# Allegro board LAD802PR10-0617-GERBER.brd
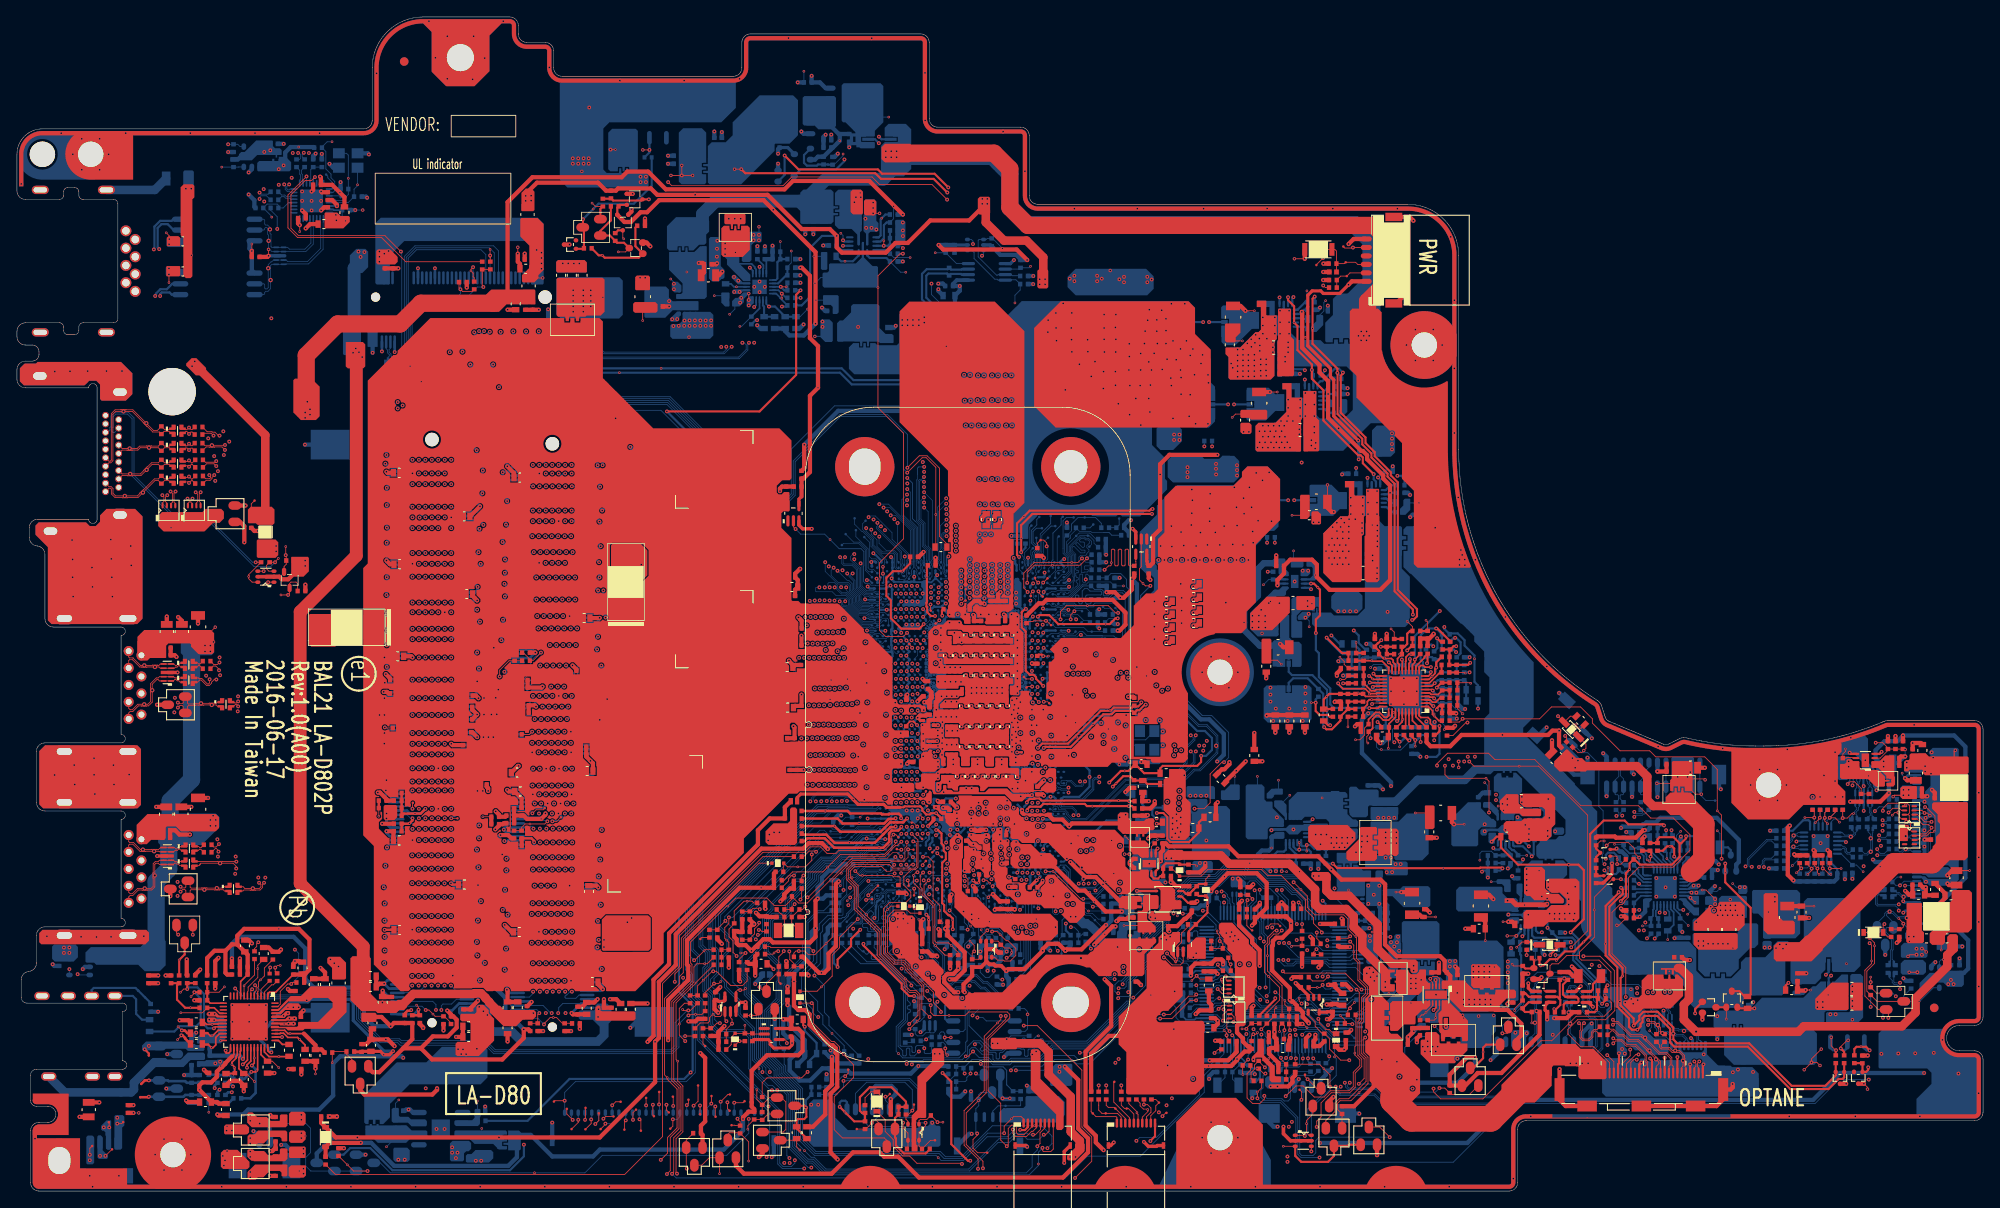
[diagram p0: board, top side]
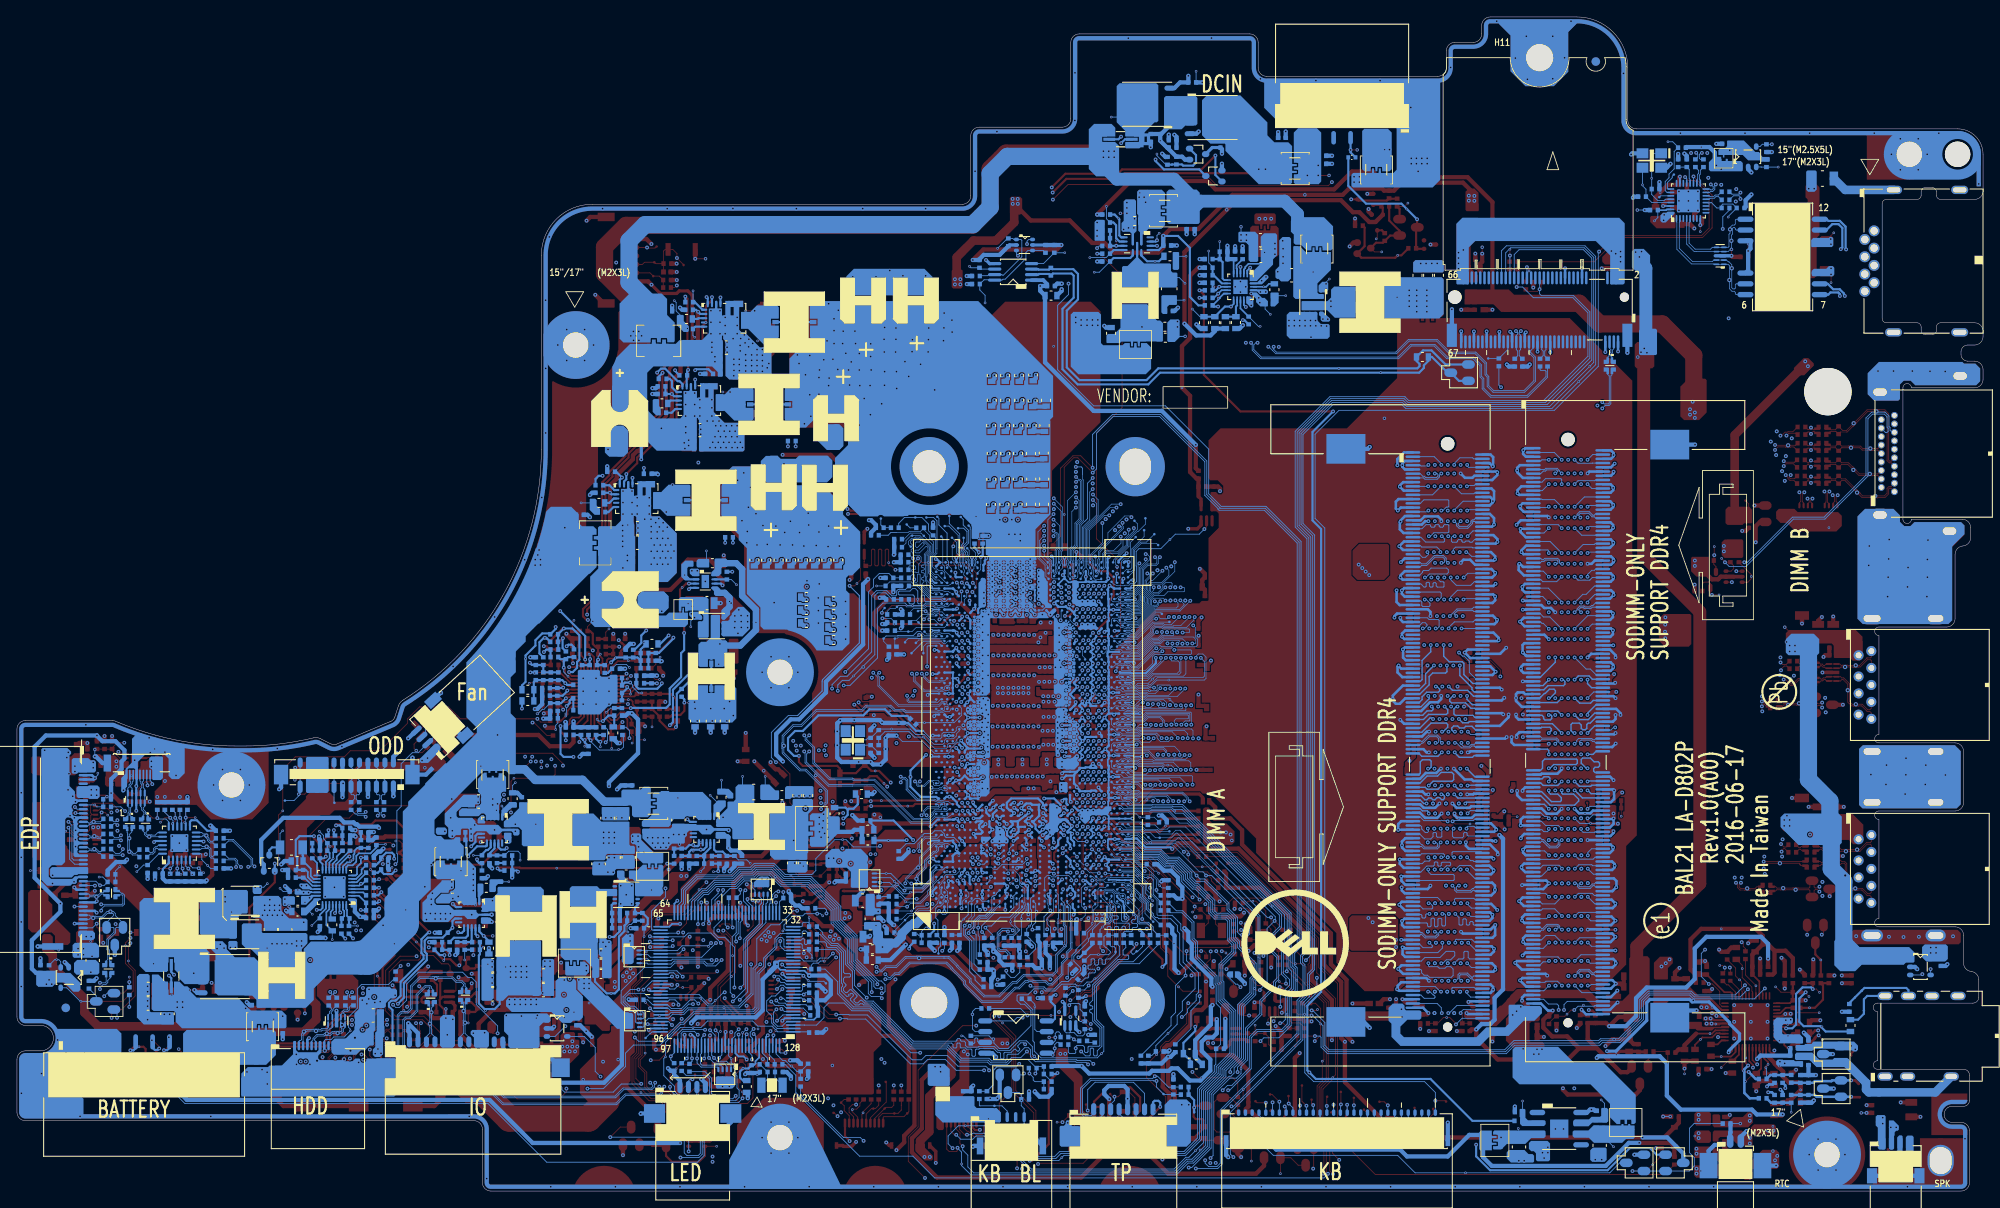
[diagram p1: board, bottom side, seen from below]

Outline 231.9 x 138.5 mm; copper layers: TOP, VCC, IN1, IN2, GND, BOTTOM. Coordinates in mm from the lower left corner of the outline.
Outline path: 0,122.3 0,117.98 arc(0.29,117.27) 1,116.98 5,116.98 arc(5.35,117.12) 5.5,117.48 5.5,117.88 arc(5.65,118.23) 6,118.38 6.8,118.38 arc(7.15,118.23) 7.3,117.88 7.3,117.48 arc(7.45,117.12) 7.8,116.98 11.4,116.98 arc(11.75,116.83) 11.9,116.48 11.9,102.92 arc(11.75,102.57) 11.4,102.42 7.8,102.42 arc(7.45,102.28) 7.3,101.92 7.3,101.52 arc(7.15,101.17) 6.8,101.02 6,101.02 arc(5.65,101.17) 5.5,101.52 5.5,101.92 arc(5.35,102.28) 5,102.42 1,102.42 arc(0.29,102.13) 0,101.42 0,100.8 arc(0.29,100.09) 1,99.8 1.8,99.8 arc(2.37,99.57) 2.6,99 2.6,98.7 arc(2.37,98.13) 1.8,97.9 1,97.9 arc(0.29,97.61) 0,96.9 0,95.75 arc(0.29,95.04) 1,94.75 8.45,94.75 arc(8.95,95.25) 9.45,94.75 9.45,79.25 arc(8.95,78.75) 8.45,79.25 2.46,79.25 arc(1.75,78.96) 1.46,78.25 1.46,77.09 arc(1.73,76.42) 2.38,76.1 arc(3.03,75.78) 3.3,75.1 3.3,67.53 arc(3.59,66.83) 4.3,66.53 12.28,66.53 arc(12.78,66.03) 12.28,65.53 12.28,53.87 arc(12.78,53.37) 12.28,52.87 3.3,52.87 arc(2.59,52.57) 2.3,51.87 2.3,45.83 arc(2.59,45.13) 3.3,44.83 12.28,44.83 arc(12.78,44.33) 12.28,43.83 12.28,32.17 arc(12.78,31.67) 12.28,31.17 3.3,31.17 arc(2.59,30.87) 2.3,30.17 2.3,26.9 arc(2.04,26.23) 1.4,25.9 arc(0.76,25.58) 0.5,24.91 0.5,22.87 arc(0.71,22.37) 1.2,22.17 12.45,22.17 arc(12.95,21.67) 12.45,21.17 12.45,15.37 arc(12.95,14.87) 12.45,14.37 2.3,14.37 arc(1.8,14.16) 1.6,13.67 1.6,10.7 arc(1.8,10.21) 2.3,10 3.65,10 arc(4.6,9.05) 3.65,8.1 2.6,8.1 arc(1.89,7.81) 1.6,7.1 1.6,1 arc(1.89,0.29) 2.6,0 176,0 arc(176.71,0.29) 177,1 177,7.3 arc(177.29,8.01) 178,8.3 230.9,8.3 arc(231.61,8.59) 231.9,9.3 231.9,15.54 arc(231.61,16.25) 230.9,16.54 229.1,16.54 arc(227.6,18.04) 229.1,19.54 230.9,19.54 arc(231.61,19.83) 231.9,20.54 231.9,54.5 arc(231.61,55.21) 230.9,55.5 220.64,55.5 arc(220.44,55.48) 220.25,55.42 arc(213.3,53.24) 206.05,52.5 205.05,52.5 arc(200.96,52.74) 196.92,53.46 arc(196.5,53.48) 196.1,53.36 194.85,52.74 arc(194.52,52.66) 194.19,52.72 187.79,55.41 arc(187.51,55.61) 187.34,55.9 186.91,57.23 arc(186.71,57.6) 186.41,57.88 arc(174.41,70.58) 170.05,87.5 170.05,110.4 arc(168.29,114.64) 164.05,116.4 120.4,116.4 arc(119.69,116.69) 119.4,117.4 119.4,124.5 arc(119.11,125.21) 118.4,125.5 108.6,125.5 arc(107.89,125.79) 107.6,126.5 107.6,135.5 arc(107.31,136.21) 106.6,136.5 86.5,136.5 arc(85.79,136.21) 85.5,135.5 85.5,132.5 arc(85.21,131.79) 84.5,131.5 64.3,131.5 arc(63.59,131.79) 63.3,132.5 63.3,134.5 arc(63.01,135.21) 62.3,135.5 60.13,135.5 arc(59.43,135.79) 59.13,136.5 59.13,137.5 arc(58.84,138.21) 58.13,138.5 47.9,138.5 arc(43.66,136.74) 41.9,132.5 41.9,126.3 arc(41.61,125.59) 40.9,125.3 3,125.3 arc(0.88,124.42) 0,122.3

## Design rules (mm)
net group 10: nets NCT7718_DXN NCT7718_DXP
net group AS-PECI: nets PECI_EC PECI_MEC1404
net group AS-PROCHOT#: nets H_PROCHOT# H_PROCHOT#_R
net group AS-VCCST_PWRGOOD: nets H_VCCST_PWRGD VCCST_PWRGD
net group CLK_PCIE_LAN_N2: nets CLK_PCIE_LAN_N2 CLK_PCIE_LAN_P2
net group CLK_PCIE_SSD_P3: nets CLK_PCIE_SSD_N3 CLK_PCIE_SSD_P3
net group CLK_PCIE_WLAN_N1: nets CLK_PCIE_WLAN_N1 CLK_PCIE_WLAN_P1
net group DDR_A_CLK0: nets DDR_A_CLK0 DDR_A_CLK#0
net group DDR_A_CLK1: nets DDR_A_CLK1 DDR_A_CLK#1
net group DDR_A_DQS0: nets DDR_A_DQS0 DDR_A_DQS#0
net group DDR_A_DQS1: nets DDR_A_DQS1 DDR_A_DQS#1
net group DDR_A_DQS2: nets DDR_A_DQS2 DDR_A_DQS#2
net group DDR_A_DQS3: nets DDR_A_DQS3 DDR_A_DQS#3
net group DDR_A_DQS4: nets DDR_A_DQS4 DDR_A_DQS#4
net group DDR_A_DQS5: nets DDR_A_DQS5 DDR_A_DQS#5
net group DDR_A_DQS6: nets DDR_A_DQS6 DDR_A_DQS#6
net group DDR_A_DQS7: nets DDR_A_DQS7 DDR_A_DQS#7
net group DDR_B_CLK0: nets DDR_B_CLK0 DDR_B_CLK#0
net group DDR_B_CLK1: nets DDR_B_CLK1 DDR_B_CLK#1
net group DDR_B_DQS0: nets DDR_B_DQS0 DDR_B_DQS#0
net group DDR_B_DQS1: nets DDR_B_DQS1 DDR_B_DQS#1
net group DDR_B_DQS2: nets DDR_B_DQS2 DDR_B_DQS#2
net group DDR_B_DQS3: nets DDR_B_DQS3 DDR_B_DQS#3
net group DDR_B_DQS4: nets DDR_B_DQS4 DDR_B_DQS#4
net group DDR_B_DQS5: nets DDR_B_DQS5 DDR_B_DQS#5
net group DDR_B_DQS6: nets DDR_B_DQS6 DDR_B_DQS#6
net group DDR_B_DQS7: nets DDR_B_DQS7 DDR_B_DQS#7
net group DIFFPAIR0: nets DMIC_CLK_EDP DMIC_DATA_EDP
net group EDP_AUX: nets EDP_AUX EDP_AUX#
net group EDP_AUX_D: nets EDP_AUX_DN EDP_AUX_DP
net group EDP_TX0: nets EDP_TX0 EDP_TX0#
net group EDP_TX0_D: nets EDP_TX0_DN EDP_TX0_DP
net group EDP_TX1: nets EDP_TX1 EDP_TX1#
net group EDP_TX1_D: nets EDP_TX1_DN EDP_TX1_DP
net group HDA_CBN/CBP/CPVEE: nets CBP CPVEE
net group HDMI_CLK: nets HDMI_CLK HDMI_CLK#
net group HDMI_CLK_R: nets HDMI_CLK#_R HDMI_CLK_R
net group HDMI_CLK_R_C: nets HDMI_CLK#_R_C HDMI_CLK_R_C
net group HDMI_DATA0: nets HDMI_DATA0 HDMI_DATA0#
net group HDMI_DATA0_R: nets HDMI_DATA0#_R HDMI_DATA0_R
net group HDMI_DATA0_R_C: nets HDMI_DATA0#_R_C HDMI_DATA0_R_C
net group HDMI_DATA1: nets HDMI_DATA1 HDMI_DATA1#
net group HDMI_DATA1_R: nets HDMI_DATA1#_R HDMI_DATA1_R
net group HDMI_DATA1_R_C: nets HDMI_DATA1#_R_C HDMI_DATA1_R_C
net group HDMI_DATA2: nets HDMI_DATA2 HDMI_DATA2#
net group HDMI_DATA2_R: nets HDMI_DATA2#_R HDMI_DATA2_R
net group HDMI_DATA2_R_C: nets HDMI_DATA2#_R_C HDMI_DATA2_R_C
net group LAN_MDI0: nets LAN_MDI0N LAN_MDI0P
net group LAN_MDI1: nets LAN_MDI1N LAN_MDI1P
net group LAN_TXN_C_PCH_RXN6: nets LAN_TXN_C_PCH_RXN6 LAN_TXP_C_PCH_RXP6
net group MDO0: nets MDO0+ MDO0-
net group MDO1: nets MDO1+ MDO1-
net group PCH_SMBCLK: nets PCH_SMBCLK PCH_SMBDATA
net group PCIE RCOMP / IREF: nets PCIE_RCOMPN PCIE_RCOMPP
net group PCIE_CRX_LANTX_6: nets PCIE_CRX_LANTX_N6 PCIE_CRX_LANTX_P6
net group PCIE_CRX_SSDTX_N12: nets PCIE_CRX_SSDTX_N12 PCIE_CRX_SSDTX_P12
net group PCIE_CRX_SSDTX_P11: nets PCIE_CRX_SSDTX_N11 PCIE_CRX_SSDTX_P11
net group PCIE_CTX_C_SSDRX_N11: nets PCIE_CTX_C_SSDRX_N11 PCIE_CTX_C_SSDRX_P11
net group PCIE_CTX_C_SSDRX_N12: nets PCIE_CTX_C_SSDRX_N12 PCIE_CTX_C_SSDRX_P12
net group PCIE_CTX_LANRX_6: nets PCIE_CTX_LANRX_N6 PCIE_CTX_LANRX_P6
net group PCIE_CTX_SSDRX_P12: nets PCIE_CTX_SSDRX_N12 PCIE_CTX_SSDRX_P12
net group PLATFORM CLOCK-DIFF: nets CLK_ITPXDP_N CLK_ITPXDP_P
net group SATA3_CRX_HDDTX_0: nets SATA3_CRX_HDDTX_N0 SATA3_CRX_HDDTX_P0
net group SATA3_CTX_HDDRX_0: nets SATA3_CTX_HDDRX_N0 SATA3_CTX_HDDRX_P0
net group SATA_CRX_ODDTX_1: nets SATA_CRX_ODDTX_N1 SATA_CRX_ODDTX_P1
net group SATA_CTX_ODDRX_1: nets SATA_CTX_ODDRX_N1 SATA_CTX_ODDRX_P1
net group SATA_RX0_R: nets SATA_RXN0_R SATA_RXP0_R
net group SATA_RX2_R: nets SATA_RXN2_R SATA_RXP2_R
net group SATA_TX0_R: nets SATA_TXN0_R SATA_TXP0_R
net group SATA_TX2_R: nets SATA_TXN2_R SATA_TXP2_R
net group SMBCLK: nets SMBCLK SMBDATA
net group SML1CLK: nets SML1CLK SML1DATA
net group THM_SML1_CLK: nets THM_SML1_CLK THM_SML1_DATA
net group USB3_CRX_C_RD_DTX_3: nets USB3_CRX_C_RD_DTX_N3 USB3_CRX_C_RD_DTX_P3
net group USB3_CRX_DTX_1: nets USB3_CRX_DTX_N1 USB3_CRX_DTX_P1
net group USB3_CRX_DTX_1_C: nets USB3_CRX_DTX_N1_C USB3_CRX_DTX_P1_C
net group USB3_CRX_DTX_2: nets USB3_CRX_DTX_N2 USB3_CRX_DTX_P2
net group USB3_CRX_DTX_2_C: nets USB3_CRX_DTX_N2_C USB3_CRX_DTX_P2_C
net group USB3_CRX_DTX_3: nets USB3_CRX_DTX_N3 USB3_CRX_DTX_P3
net group USB3_CRX_L_DTX_3: nets USB3_CRX_L_DTX_N3 USB3_CRX_L_DTX_P3
net group USB3_CRX_RD_DTX_3: nets USB3_CRX_RD_DTX_N3 USB3_CRX_RD_DTX_P3
net group USB3_CTX_C_DRX_3: nets USB3_CTX_C_DRX_N3 USB3_CTX_C_DRX_P3
net group USB3_CTX_C_RD_DRX_3: nets USB3_CTX_C_RD_DRX_N3 USB3_CTX_C_RD_DRX_P3
net group USB3_CTX_DRX_1: nets USB3_CTX_DRX_N1 USB3_CTX_DRX_P1
net group USB3_CTX_DRX_1_C: nets USB3_CTX_DRX_N1_C USB3_CTX_DRX_P1_C
net group USB3_CTX_DRX_1_R: nets USB3_CTX_DRX_N1_R USB3_CTX_DRX_P1_R
net group USB3_CTX_DRX_2: nets USB3_CTX_DRX_N2 USB3_CTX_DRX_P2
net group USB3_CTX_DRX_2_C: nets USB3_CTX_DRX_N2_C USB3_CTX_DRX_P2_C
net group USB3_CTX_DRX_2_R: nets USB3_CTX_DRX_N2_R USB3_CTX_DRX_P2_R
net group USB3_CTX_DRX_3: nets USB3_CTX_DRX_N3 USB3_CTX_DRX_P3
net group USB3_CTX_L_DRX_3: nets USB3_CTX_L_DRX_N3 USB3_CTX_L_DRX_P3
net group USB3_CTX_RD_DRX_3: nets USB3_CTX_RD_DRX_N3 USB3_CTX_RD_DRX_P3
net group USB_CAMERA_EDP: nets USB_CAMERA_EDP USB_CAMERA_EDP#
net group USB_P1: nets USB_PN1 USB_PP1
net group USB_P1_C: nets USB_PN1_C USB_PP1_C
net group USB_P2: nets USB_PN2 USB_PP2
net group USB_P2_C: nets USB_PN2_C USB_PP2_C
net group USB_P3: nets USB_PN3 USB_PP3
net group USB_P3_C: nets USB_PN3_C USB_PP3_C
net group USB_P5: nets USB_PN5 USB_PP5
net group USB_P7: nets USB_PN7 USB_PP7
net group USB_P8: nets USB_PN8 USB_PP8
net group USB_P8_R: nets USB_PN8_R USB_PP8_R
net group USB_PN7_TPNL: nets USB_PN7_TPNL USB_PP7_TPNL
net group AS-BPM#[3:0]: nets XDP_OBS0_R XDP_OBS1_R XDP_OBS2_R XDP_OBS3_R
net group AS-CATERR#: nets H_CATERR#
net group AS-SVID: nets H_CPU_SVIDALRT# VIDALERT_N VIDSCLK VIDSOUT
net group AS-THERMTRIP#: nets H_THERMTRIP#
net group DDR_COMP_20_25: nets SM_RCOMP0 SM_RCOMP1 SM_RCOMP2
net group DDR_RESET: nets DDR4_DRAMRST#
net group DDRADD_10(11)_20: nets DDR_A_ACT# DDR_A_ALERT# DDR_A_BG0 DDR_A_BG1 DDR_A_BS0 DDR_A_BS1 DDR_A_CAS# DDR_A_MA0 DDR_A_MA1 DDR_A_MA2 DDR_A_MA3 DDR_A_MA4 DDR_A_MA5 DDR_A_MA6 DDR_A_MA7 DDR_A_MA8 DDR_A_MA9 DDR_A_MA10 DDR_A_MA11 DDR_A_MA12 DDR_A_MA13 DDR_A_PAR DDR_A_RAS# DDR_A_WE# DDR_B_ACT# DDR_B_ALERT# DDR_B_BG0 DDR_B_BG1 DDR_B_BS0 DDR_B_BS1 DDR_B_CAS# DDR_B_MA0 DDR_B_MA1 DDR_B_MA2 DDR_B_MA3 DDR_B_MA4 DDR_B_MA5 DDR_B_MA6 DDR_B_MA7 DDR_B_MA8 DDR_B_MA9 DDR_B_MA10 DDR_B_MA11 DDR_B_MA12 DDR_B_MA13 DDR_B_PAR DDR_B_RAS# DDR_B_WE#
net group DDRB_D3: nets DDR_B_D24 DDR_B_D25 DDR_B_D26 DDR_B_D27 DDR_B_D28 DDR_B_D29 DDR_B_D30 DDR_B_D31
net group DDRCTL_10(11)_20: nets DDR_A_CKE0 DDR_A_CKE1 DDR_A_CKE2 DDR_A_CKE3 DDR_A_CS#0 DDR_A_CS#1 DDR_A_ODT0 DDR_A_ODT1 DDR_B_CKE0 DDR_B_CKE1 DDR_B_CKE2 DDR_B_CKE3 DDR_B_CS#0 DDR_B_CS#1 DDR_B_ODT0 DDR_B_ODT1
net group DDRD0_19(8.5)_20: nets DDR_A_D0 DDR_A_D1 DDR_A_D2 DDR_A_D3 DDR_A_D4 DDR_A_D5 DDR_A_D6 DDR_A_D7 DDR_A_D16 DDR_A_D17 DDR_A_D18 DDR_A_D19 DDR_A_D20 DDR_A_D21 DDR_A_D22 DDR_A_D23 DDR_A_D32 DDR_A_D33 DDR_A_D34 DDR_A_D35 DDR_A_D36 DDR_A_D37 DDR_A_D38 DDR_A_D39 DDR_A_D48 DDR_A_D49 DDR_A_D50 DDR_A_D51 DDR_A_D52 DDR_A_D53 DDR_A_D54 DDR_A_D55 DDR_B_D0 DDR_B_D1 DDR_B_D2 DDR_B_D3 DDR_B_D4 DDR_B_D5 DDR_B_D6 DDR_B_D7 DDR_B_D16 DDR_B_D17 DDR_B_D18 DDR_B_D19 DDR_B_D20 DDR_B_D21 DDR_B_D22 DDR_B_D23 DDR_B_D32 DDR_B_D33 DDR_B_D34 DDR_B_D35 DDR_B_D36 DDR_B_D37 DDR_B_D38 DDR_B_D39 DDR_B_D48 DDR_B_D49 DDR_B_D50 DDR_B_D51 DDR_B_D52 DDR_B_D53 DDR_B_D54 DDR_B_D55
net group DDRD1_19(8.5)_20: nets DDR_A_D8 DDR_A_D9 DDR_A_D10 DDR_A_D11 DDR_A_D12 DDR_A_D13 DDR_A_D14 DDR_A_D15 DDR_A_D24 DDR_A_D25 DDR_A_D26 DDR_A_D27 DDR_A_D28 DDR_A_D29 DDR_A_D30 DDR_A_D31 DDR_A_D40 DDR_A_D41 DDR_A_D42 DDR_A_D43 DDR_A_D44 DDR_A_D45 DDR_A_D46 DDR_A_D47 DDR_A_D56 DDR_A_D57 DDR_A_D58 DDR_A_D59 DDR_A_D60 DDR_A_D61 DDR_A_D62 DDR_A_D63 DDR_B_D8 DDR_B_D9 DDR_B_D10 DDR_B_D11 DDR_B_D12 DDR_B_D13 DDR_B_D14 DDR_B_D15 DDR_B_D40 DDR_B_D41 DDR_B_D42 DDR_B_D43 DDR_B_D44 DDR_B_D45 DDR_B_D46 DDR_B_D47 DDR_B_D56 DDR_B_D57 DDR_B_D58 DDR_B_D59 DDR_B_D60 DDR_B_D61 DDR_B_D62 DDR_B_D63
net group EDP_COMP: nets EDP_COMP
net group HDA HEADPHONE JACK: nets RING2 RING2_R SLEEVE_R
net group HDA SPEAKER: nets AUD_SPK_L+ AUD_SPK_L+_C AUD_SPK_L- AUD_SPK_L-_C AUD_SPK_R+ AUD_SPK_R+_C AUD_SPK_R- AUD_SPK_R-_C
net group HDA_ANALOG IO: nets AUD_HP1_JACK_L AUD_HP1_JACK_L1 AUD_HP1_JACK_R AUD_HP1_JACK_R1 CBN HPOUT_L HPOUT_R LINE1-L_C LINE1-L_R LINE1_L LINE1_R
net group HDMI_DDC: nets DDC_CLK_HDMI DDC_DATA_HDMI PCH_HDMI_CLK PCH_HDMI_DATA
net group HIGH DEFINITION AUDIO: nets DMIC_CLK HDA_BIT_CLK HDA_CODEC_BITCLK HDA_CODEC_RST# HDA_CODEC_SDOUT HDA_CODEC_SYNC HDA_RST# HDA_SDIN0 HDA_SDOUT HDA_SYNC
net group I2C: nets I2C_SCL_TP I2C_SCL_TP_Q I2C_SDA_TP I2C_SDA_TP_Q
net group KB: nets KSI0 KSI1 KSI2 KSI3 KSI4 KSI5 KSI6 KSI7 KSO0 KSO1 KSO2 KSO3 KSO4 KSO5 KSO6 KSO7 KSO8 KSO9 KSO10 KSO11 KSO12 KSO13 KSO14 KSO15 KSO16
net group LPC: nets CLK_PCI_LPC_MEC LPC_LAD0 LPC_LAD1 LPC_LAD2 LPC_LAD3 LPC_LFRAME#
net group PCIE: nets PCIE_CRX_WLANTX_N5 PCIE_CRX_WLANTX_P5 PCIE_CTX_SSDRX_N11 PCIE_CTX_WLANRX_N5 PCIE_CTX_WLANRX_N5_C PCIE_CTX_WLANRX_P5 PCIE_CTX_WLANRX_P5_C PCIE_PTX_LANRX_P6_C
net group PCIE_CTX_SSDRX_N11: nets PCIE_CTX_SSDRX_P11
net group PCIE_PTX_LANRX_6_C: nets PCIE_PTX_LANRX_N6_C
net group RTC: nets PCH_RTCRST# PCH_RTCX1 PCH_RTCX2 PCH_RTCX2_R SRTCRST# SUSCLK
net group SMBUS: nets PCH_SMB_ALERT# SML0_SMBCLK SML0_SMBDATA
net group SPI: nets EC_SPI_CLK EC_SPI_CS0# EC_SPI_MISO EC_SPI_MOSI PCH_SPI_CLK_0_R PCH_SPI_CLK_R PCH_SPI_CLK_R1 PCH_SPI_CS#0_R1 PCH_SPI_D0_0_R PCH_SPI_D0_R PCH_SPI_D0_R1 PCH_SPI_D1_0_R PCH_SPI_D1_R PCH_SPI_D1_R1 PCH_SPI_D2_0_R PCH_SPI_D2_R PCH_SPI_D2_R1 PCH_SPI_D3_0_R PCH_SPI_D3_R PCH_SPI_D3_R1
net group SRCCLKREQ/ CLKOUT_LPC: nets CLK_PCIE_LAN_REQ# CLK_PCIE_LAN_REQ#_R CLK_PCIE_WLAN_REQ# CLK_PCIE_WLAN_REQ#_R PCI_CLK_LPC1
net group USB20: nets USB_PN6 USB_PN6_C USB_PP6 USB_PP6_C
net group XCLK_BIASREF: nets XCLK_BIASREF
net group XDP: nets CPU_XDP_TCK0 PCH_JTAG_TCK1 PCH_RSMRST#_Q SOC_XDP_TDI SOC_XDP_TDO SOC_XDP_TMS SOC_XDP_TRST# XDP_HOOK0 XDP_ITP_PMODE XDP_PRDY# XDP_PREQ# XDP_PRSENT_CPU XDP_SPI_IO2 XDP_SPI_SI
net group XDP_OBS_CLK_1P: nets CFG16 CFG17 CFG18 CFG19
net group XDP_OBSDATA: nets CFG0 CFG1 CFG2 CFG3 CFG4 CFG5 CFG6 CFG7 CFG8 CFG9 CFG10 CFG11 CFG12 CFG13 CFG14 CFG15 CFG_RCOMP
net group XTAL24_IN/OUT: nets XTAL24_IN XTAL24_OUT XTAL24_OUT_R
nets with their own width: min track width 0.254; nets +1.0V_APLL +1.0V_VCCST +1.0V_VCCST_C +1.0V_VCCSTG +1.0V_VCCSTG_C +1.8V_PRIM +3.3V_ALW_DSW +3.3V_SPI +3VLP +TP_VDD
nets with their own width: min track width 0.381; nets +1.8V_AVDD +1.8V_CPVDD
nets with their own width: min track width 0.508; nets +1.0V_AMPHYPLL +1.0V_APLLEBB +1.0V_MPHYGT +1.0V_PRIM +1.0V_SRAM +1.0VS_VCCIO +1.0VS_VCCOPC +1.2VP +2.5VP +3V_DVDD +3VALW +3VALW_PCH +3VALWP +3VS +3VS_CAM +5V_CAM +5V_KB_BL +5VALW +5VALWP +5VS +19VB +DCBAT_LCD +LAN_VDD10 +LAN_VDDREG +RTC_CELL +V_DDR_REFA +V_DDR_REFA_R +VCC_CORE +VCC_GT +VCC_SA AUD_AGND GND IR_GND
nets with their own width: min track width 1.016; nets +TPAN_VDD +TPAN_VDD_F
nets with their own width: min track width 1.524; nets +0.6VSP +5V_AVDD
nets with their own width: min track width 2.032; nets +3.3V_WLAN USB20_VCCA USB30_VCCA
nets with their own width: min track width 2.413; nets +LCDVDD_LCD
nets with their own width: min track width 2.54; nets +5V_PVDD

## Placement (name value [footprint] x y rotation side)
C1  0.47U_0402_6.3V6K  [C_0402]  35.88 8.79 0 top
C2  0.1U_0402_16V7K  [C_0402]  223.78 47.46 0 top
C3  1U_0402_10V6K  [C_0402]  223.78 46.57 0 top
C4  0.1U_0603_50V7K  [C_0603]  224.75 51.27 90 top
C5  1000P_0402_50V7K  [C_0402]  223.6 51.19 90 top
C6  0.1U_0402_16V7K  [C_0402]  220.8 42.12 0 bottom
C7  0.1U_0402_16V7K  [C_0402]  220.8 41.24 0 bottom
C8  0.1U_0402_16V7K  [C_0402]  220.8 40.35 0 bottom
C9  0.1U_0402_16V7K  [C_0402]  220.8 39.46 0 bottom
C10  0.1U_0402_16V7K  [C_0402]  220.8 43.01 0 bottom
C11  0.1U_0402_16V7K  [C_0402]  220.8 43.9 0 bottom
C13  10P_0402_50V8J  [C_0402]  220.29 37.36 0 bottom
C14  33P_0402_50V8J  [C_0402]  224.49 36.14 180 top
C15  4.7U_0603_6.3V6K  [C_0603]  225 34.94 180 top
C16  10P_0402_50V8J  [C_0402]  222.01 30.9 270 top
C17  1U_0402_6.3V6K  [C_0402]  229.13 25.72 90 bottom
C18  .1U_0402_16V7K  [C_0402]  87.9 8.39 90 top
C19  0.1U_0402_16V7K  [C_0402]  103.98 9.93 180 top
C20  10U_0603_6.3V6M  [C_0603]  110.64 105.63 180 bottom
C21  0.1U_0402_16V7K  [C_0402]  110.4 106.76 180 bottom
C22  470P_0603_50V8J  [C_0603]  65.43 98.39 0 bottom
C23  2200P_0402_50V7K  [C_0402]  109.95 107.99 90 bottom
C24  0.1U_0402_16V7K  [C_0402]  118.33 106.99 0 bottom
C25  0.1U_0402_16V7K  [C_0402]  118.33 107.94 0 bottom
C26  10P_0402_50V8J  [C_0402]  95.5 12.25 90 bottom
C27  10P_0402_50V8J  [C_0402]  95.5 11.39 270 bottom
C30  22U_0805_10V6M  [C_0805]  182.17 50.47 135 top
C32  0.1U_0402_16V7K  [C_0402]  111.64 14.5 0 bottom
C33  100P_0402_50V8J  [C_0402]  109.86 12.91 0 bottom
C34  .1U_0402_16V7K  [C_0402]  120.28 10.86 90 bottom
CA1  10U_0603_10V6M  [C_0603]  35.01 23.65 90 top
CA2  .1U_0402_16V7K  [C_0402]  32.85 22.68 90 top
CA3  10U_0603_10V6M  [C_0603]  36.34 23.65 90 top
CA4  .1U_0402_16V7K  [C_0402]  33.48 19.63 90 top
CA5  4.7U_0603_6.3V6K  [C_0603]  26.88 28.21 90 top
CA6  .1U_0402_16V7K  [C_0402]  27.21 26.44 180 top
CA7  .1U_0402_16V7K  [C_0402]  22.45 22.5 180 top
CA10  .1U_0402_16V7K  [C_0402]  23.59 13.93 180 top
CA11  4.7U_0603_10V6K  [C_0603]  22.94 10.5 180 top
CA12  4.7U_0603_6.3V6K  [C_0603]  35.21 16.7 270 top
CA13  4.7U_0603_6.3V6K  [C_0603]  41.75 16.48 90 top
CA14  .1U_0402_16V7K  [C_0402]  40.65 16.42 90 top
CA15  4.7U_0603_6.3V6K  [C_0603]  33.67 25.61 90 top
CA16  .1U_0402_16V7K  [C_0402]  32.59 25.54 90 top
CA17  .1U_0402_16V7K  [C_0402]  27.21 25.55 180 top
CA20  4.7U_0603_6.3V6K  [C_0603]  24.66 12.47 90 top
CA21  10U_0603_6.3V6M  [C_0603]  33.98 15.31 90 top
CA22  4.7U_0603_6.3V6K  [C_0603]  29.1 28.73 270 top
CA23  2.2U_0603_6.3V6K  [C_0603]  26.75 13.87 270 top
CA24  1U_0603_16V7  [C_0603]  32.09 15.9 90 top
CA25  1U_0603_16V7  [C_0603]  29.56 13.92 90 top
CA26  10U_0603_6.3V6M  [C_0603]  21.86 19.89 180 top
CA27  1000P_0402_50V7K  [C_0402]  30.5 6.77 270 top
CA28  1000P_0402_50V7K  [C_0402]  30.5 7.82 90 top
CA29  1000P_0402_50V7K  [C_0402]  30.5 2.7 270 top
CA30  1000P_0402_50V7K  [C_0402]  30.5 4.08 90 top
CA31  0.1U_0402_16V7K  [C_0402]  21.53 21.61 0 top
CA32  10U_0603_10V6M  [C_0603]  21.86 17.35 180 top
CA33  10U_0603_10V6M  [C_0603]  21.86 18.62 180 top
CA34  100P_0402_50V8J  [C_0402]  20.59 12.77 90 bottom
CA35  100P_0402_50V8J  [C_0402]  20.59 11.33 270 bottom
CA36  100P_0402_50V8J  [C_0402]  20.59 15.78 270 bottom
CA37  100P_0402_50V8J  [C_0402]  20.59 16.84 90 bottom
CC1  0.1U_0402_16V7K  [C_0402]  90.74 82.19 90 top
CC2  33P_0402_50V8J  [C_0402]  104.77 18.43 270 bottom
CC3  0.1U_0402_25V6  [C_0402]  109.98 22.77 0 bottom
CC4  1U_0402_6.3V6K  [C_0402]  92.54 26.5 270 top
CC5  1U_0402_6.3V6K  [C_0402]  89.86 26.49 0 top
CC6  12P_0402_50V8J  [C_0402]  131.21 53.46 90 bottom
CC7  12P_0402_50V8J  [C_0402]  131.21 52.6 270 bottom
CC8  6.8P_0402_50V8C  [C_0402]  91.38 32.33 0 top
CC9  6.8P_0402_50V8C  [C_0402]  90.52 32.33 180 top
CC10  1U_0402_6.3V6K  [C_0402]  83.66 18.51 180 top
CC11  0.1U_0402_10V7K  [C_0402]  82.38 22.54 90 top
CC12  0.1U_0402_16V7K  [C_0402]  91.29 19.15 270 top
CC13  0.1U_0402_16V7K  [C_0402]  133.5 73.75 270 top
CC14  1U_0402_6.3V6K  [C_0402]  86.75 18.6 270 top
CC15  100P_0402_50V8J  [C_0402]  130.25 77.36 0 bottom
CC16  22P_0402_50V8J  [C_0402]  81.17 21.23 270 top
CC17  10U_0402_6.3V6M  [C_0402]  115.72 68.7 90 top
CC18  10U_0402_6.3V6M  [C_0402]  111.45 68.62 0 top
CC19  10U_0402_6.3V6M  [C_0402]  110.21 68.65 180 top
CC20  1U_0402_6.3V6K  [C_0402]  114.83 68.7 90 top
CC21  1U_0402_6.3V6K  [C_0402]  113.43 68.7 90 top
CC22  1U_0402_6.3V6K  [C_0402]  114.65 67.25 180 top
CC23  1U_0402_6.3V6K  [C_0402]  115.64 67.25 0 top
CC24  1U_0402_6.3V6K  [C_0402]  111.96 67.25 0 top
CC25  1U_0402_6.3V6K  [C_0402]  116.61 68.7 90 top
CC26  10U_0402_6.3V6M  [C_0402]  91.71 52.51 90 top
CC27  10U_0402_6.3V6M  [C_0402]  92.54 56.32 90 top
CC28  10U_0402_6.3V6M  [C_0402]  91.64 66.36 0 top
CC29  10U_0402_6.3V6M  [C_0402]  92.03 48.76 90 top
CC30  10U_0402_6.3V6M  [C_0402]  91.14 48.76 90 top
CC31  10U_0402_6.3V6M  [C_0402]  89.92 53.41 0 top
CC32  1U_0402_6.3V6K  [C_0402]  104.9 53.91 90 top
CC33  1U_0402_6.3V6K  [C_0402]  104.92 57.02 90 top
CC34  1U_0402_6.3V6K  [C_0402]  92.47 61.15 90 top
CC35  1U_0402_6.3V6K  [C_0402]  91.78 69.27 90 top
CC36  22U_0603_6.3V6M  [C_0603]  90.19 57.03 0 top
CC37  22U_0603_6.3V6M  [C_0603]  90.13 61.79 0 top
CC38  22U_0603_6.3V6M  [C_0603]  90.7 71.25 0 top
CC39  10U_0402_6.3V6M  [C_0402]  90.87 72.4 0 top
CC40  1U_0402_6.3V6K  [C_0402]  105.35 47.89 0 top
CC41  1U_0402_6.3V6K  [C_0402]  131.83 43.37 90 top
CC42  1U_0402_6.3V6K  [C_0402]  120.35 46.79 90 top
CC43  1U_0402_6.3V6K  [C_0402]  91.62 64.36 0 top
CC44  1U_0402_6.3V6K  [C_0402]  132.73 43.37 90 top
CC45  1U_0402_6.3V6K  [C_0402]  106.65 50.62 180 top
CC46  1U_0402_6.3V6K  [C_0402]  107.65 57.11 270 top
CC47  1U_0402_6.3V6K  [C_0402]  107.08 49.74 270 top
CC48  1U_0402_6.3V6K  [C_0402]  107.97 49.74 270 top
CC49  10U_0402_6.3V6M  [C_0402]  107.85 58.36 180 top
CC50  10U_0402_6.3V6M  [C_0402]  107.46 59.24 90 top
CC51  1U_0402_6.3V6K  [C_0402]  105.86 30.04 0 top
CC52  1U_0402_6.3V6K  [C_0402]  105.86 29.15 0 top
CC53  1U_0402_6.3V6K  [C_0402]  105.86 28.26 0 top
CC54  1U_0402_6.3V6K  [C_0402]  107.91 26.86 90 top
CC55  1U_0402_6.3V6K  [C_0402]  117.61 41.99 180 top
CC56  1U_0402_6.3V6K  [C_0402]  107.54 30.94 180 top
CC57  1U_0402_6.3V6K  [C_0402]  110 44.06 90 top
CC58  1U_0402_6.3V6K  [C_0402]  115.08 46.22 90 top
CC59  47U_0805_6.3V6M  [C_0805]  130.41 30 0 bottom
CC60  1U_0402_6.3V6K  [C_0402]  115.48 38.5 180 top
CC61  8.2P_0402_50V8D  [C_0402]  109.02 43.92 180 top
CC62  1U_0402_6.3V6K  [C_0402]  110.15 45.92 180 top
CC63  1U_0402_6.3V6K  [C_0402]  131.24 43.71 0 bottom
CC64  1U_0402_6.3V6K  [C_0402]  111.98 41.33 270 top
CC65  1P_0402_50V8  [C_0402]  90.57 43.96 270 top
CC66  1U_0402_6.3V6K  [C_0402]  113.53 40.51 0 top
CC67  1U_0402_6.3V6K  [C_0402]  133.2 36.55 0 bottom
CC68  1U_0402_6.3V6K  [C_0402]  111.25 39.56 0 top
CC69  0.1U_0402_10V7K  [C_0402]  103.97 36.1 270 top
CC70  0.1U_0402_10V7K  [C_0402]  90.75 40.39 90 top
CC71  1U_0402_6.3V6K  [C_0402]  89.85 40.39 90 top
CC72  1U_0402_6.3V6K  [C_0402]  116.86 33.26 90 top
CC73  0.1U_0402_10V7K  [C_0402]  130.27 31.33 90 bottom
CC74  47U_0805_6.3V6M  [C_0805]  131.31 34.26 0 bottom
CC75  1U_0402_6.3V6K  [C_0402]  117.67 38.72 180 top
CC76  47U_0603_6.3V6M  [C_0603]  140.01 44.09 0 top
CC77  47U_0603_6.3V6M  [C_0603]  131.9 50.35 0 top
CC78  0.1U_0402_10V7K  [C_0402]  113.49 42.5 270 top
CC79  1U_0402_6.3V6K  [C_0402]  133.22 37.42 0 bottom
CC80  22U_0603_6.3V6M  [C_0603]  93.49 14.94 180 bottom
CC81  22U_0603_6.3V6M  [C_0603]  94.32 16.21 180 bottom
CC82  8.2P_0402_50V8D  [C_0402]  131.76 48.47 270 top
CC83  0.1U_0603_25V7K  [C_0603]  132.8 48.42 270 top
CC84  47U_0603_6.3V6M  [C_0603]  133 46.83 180 bottom
CC85  1U_0402_6.3V6K  [C_0402]  109.76 30.18 180 top
CC86  1U_0402_6.3V6K  [C_0402]  110.97 34.29 180 top
CC87  1U_0402_6.3V6K  [C_0402]  115.97 33.27 90 top
CC88  10P_0402_50V8J  [C_0402]  90.46 16.78 180 bottom
CC89  1P_0402_50V8  [C_0402]  81.82 19.21 270 top
CC90  100P_0402_50V8J  [C_0402]  92.54 83.1 180 top
CD1  10U_0603_6.3V6M~D  [C_0603]  72.41 20.72 90 top
CD2  10U_0603_6.3V6M~D  [C_0603]  71.2 20.72 90 top
CD3  1U_0402_6.3V6K~D  [C_0402]  70.12 20.71 90 top
CD4  1U_0402_6.3V6K~D  [C_0402]  69.23 20.71 90 top
CD5  1U_0402_6.3V6K~D  [C_0402]  60.15 20.9 90 top
CD6  10U_0603_6.3V6M~D  [C_0603]  57.87 19.96 270 top
CD7  10U_0603_6.3V6M~D  [C_0603]  57.87 20.92 90 top
CD8  10U_0603_6.3V6M~D  [C_0603]  59.07 20.92 90 top
CD9  0.1U_0402_16V7K~D  [C_0402]  66.12 20.84 90 top
CD10  2.2U_0603_6.3V6K~D  [C_0603]  67.2 20.85 90 top
CD11  1U_0402_6.3V6K~D  [C_0402]  58.62 40.72 0 top
CD12  1U_0402_6.3V6K~D  [C_0402]  66.24 51.52 0 top
CD13  1U_0402_6.3V6K~D  [C_0402]  66.9 61.36 180 top
CD14  1U_0402_6.3V6K~D  [C_0402]  66.24 52.41 0 top
CD15  1U_0402_6.3V6K~D  [C_0402]  59.44 56.41 0 top
CD16  1U_0402_6.3V6K~D  [C_0402]  59.44 57.3 0 top
CD17  1U_0402_6.3V6K~D  [C_0402]  59.32 60.28 0 top
CD18  1U_0402_6.3V6K~D  [C_0402]  59.32 59.39 0 top
CD19  10U_0603_6.3V6M~D  [C_0603]  60.09 47.14 180 top
CD20  10U_0603_6.3V6M~D  [C_0603]  66.54 49.54 0 top
CD21  10U_0603_6.3V6M~D  [C_0603]  59.96 30.56 180 top
CD22  10U_0603_6.3V6M~D  [C_0603]  66.19 67.59 0 top
CD23  10U_0603_6.3V6M~D  [C_0603]  60.03 84.16 180 top
CD24  10U_0603_6.3V6M~D  [C_0603]  67.14 24.66 0 top
CD25  10U_0603_6.3V6M~D  [C_0603]  67.46 34.63 90 top
CD26  10U_0603_6.3V6M~D  [C_0603]  59.71 49.36 180 top
CD27  330U_D2_2V_Y  [C_D2]  42.09 66.5 180 top
CD28  0.1U_0402_16V7K~D  [C_0402]  59.52 44.3 90 top
CD29  0.1U_0402_16V7K~D  [C_0402]  59.58 63.52 0 top
CD30  0.022U_0402_25V7K  [C_0402]  56.86 43.27 180 top
CD31  1U_0402_6.3V6K~D  [C_0402]  44.21 21.98 90 top
CD32  10U_0603_6.3V6M~D  [C_0603]  40.98 24.08 0 top
CD33  10U_0603_6.3V6M~D  [C_0603]  40.98 25.35 0 top
CD34  10U_0603_6.3V6M~D  [C_0603]  43.14 21.55 90 top
CD35  1U_0402_6.3V6K~D  [C_0402]  52.66 20.52 90 top
CD36  1U_0402_6.3V6K~D  [C_0402]  53.55 20.52 90 top
CD37  10U_0603_6.3V6M~D  [C_0603]  54 19.44 180 top
CD38  10U_0603_6.3V6M~D  [C_0603]  54 18.18 180 top
CD39  0.1U_0402_16V7K~D  [C_0402]  45.74 19.82 90 top
CD40  2.2U_0603_6.3V6K~D  [C_0603]  41.93 20.53 270 top
CD41  1U_0402_6.3V6K~D  [C_0402]  44.93 58.7 180 top
CD42  1U_0402_6.3V6K~D  [C_0402]  44.93 60.29 180 top
CD43  1U_0402_6.3V6K~D  [C_0402]  54.49 47.96 0 top
CD44  1U_0402_6.3V6K~D  [C_0402]  53.56 52.6 180 top
CD45  1U_0402_6.3V6K~D  [C_0402]  52.65 54.13 0 top
CD46  1U_0402_6.3V6K~D  [C_0402]  52.77 55.65 0 top
CD47  1U_0402_6.3V6K~D  [C_0402]  52.77 57.11 0 top
CD48  1U_0402_6.3V6K~D  [C_0402]  52.84 58.44 0 top
CD49  10U_0603_6.3V6M~D  [C_0603]  53.49 36.16 180 top
CD50  10U_0603_6.3V6M~D  [C_0603]  52.03 79.59 0 top
CD51  10U_0603_6.3V6M~D  [C_0603]  44.21 63.08 0 top
CD52  10U_0603_6.3V6M~D  [C_0603]  45.87 73.94 180 top
CD53  10U_0603_6.3V6M~D  [C_0603]  45.8 84.73 180 top
CD54  10U_0603_6.3V6M~D  [C_0603]  45.8 41.36 180 top
CD55  10U_0603_6.3V6M~D  [C_0603]  52.34 70.44 0 top
CD56  10U_0603_6.3V6M~D  [C_0603]  45.87 30.82 180 top
CD57  330U_D2_2V_Y  [C_D2]  71.84 68.64 90 top
CD58  0.1U_0402_16V7K~D  [C_0402]  45.37 44.28 180 top
CD59  0.022U_0402_25V7K  [C_0402]  43.59 46.06 180 top
CE1  0.1U_0402_10V7K  [C_0402]  150.06 19.71 0 top
CE2  0.1U_0402_10V7K  [C_0402]  149.7 14.95 180 top
CE3  10P_0402_50V8J  [C_0402]  143.36 14.04 0 bottom
CE4  10P_0402_50V8J  [C_0402]  142.49 14.04 180 bottom
CE5  10U_0603_6.3V6M  [C_0603]  156.36 23.32 270 top
CE6  0.1U_0402_10V7K  [C_0402]  140.87 26.82 270 top
CE7  1000P_0402_50V7K  [C_0402]  146.02 33.22 270 top
CE8  1000P_0402_50V7K  [C_0402]  149.69 33.31 270 top
CE9  0.1U_0402_25V6  [C_0402]  155.46 31.51 0 top
CE10  0.1U_0402_25V6  [C_0402]  155.42 24.38 0 top
CE11  0.1U_0402_25V6  [C_0402]  152.03 17.1 0 top
CE12  0.1U_0402_25V6  [C_0402]  140.86 20.39 90 top
CE13  0.1U_0402_25V6  [C_0402]  146.74 17.59 0 top
CE14  0.1U_0402_10V7K  [C_0402]  145.26 14.84 270 bottom
CE15  0.1U_0402_25V6  [C_0402]  148.8 32.4 90 top
CE16  100P_0402_50V8J  [C_0402]  154.39 15.09 270 bottom
CE17  0.1U_0402_25V6  [C_0402]  156.74 18.7 270 top
CE18  0.1U_0402_10V7K  [C_0402]  151.58 28.93 270 top
CE19  0.047U_0402_16V4Z  [C_0402]  145.18 34.94 90 top
CE20  0.1U_0402_25V6  [C_0402]  140 26.83 270 top
CE21  0.1U_0402_25V6  [C_0402]  146.77 16.7 0 top
CE22  0.1U_0402_10V7K  [C_0402]  155.18 21.15 90 top
CE23  0.1U_0402_25V6  [C_0402]  140.86 29.51 180 top
CE24  1U_0603_16V7  [C_0603]  140.58 25 270 top
CE25  2200P_0402_25V7K  [C_0402]  149.45 17.93 180 top
CE26  47P_0402_50V8J  [C_0402]  154.2 18.57 270 top
CE27  0.047U_0402_16V4Z  [C_0402]  151.48 33.3 180 top
CE28  220P_0402_50V8J  [C_0402]  145.07 33.23 180 top
CE29  0.1U_0402_10V7K  [C_0402]  153.76 29.17 180 top
CE30  2200P_0402_25V7K  [C_0402]  148.32 20.65 270 top
CE31  1000P_0402_50V7K  [C_0402]  152.93 27.91 270 top
CE32  100P_0402_50V8J  [C_0402]  142.07 17.63 270 top
CE33  1U_0402_6.3V6K  [C_0402]  138.58 15.02 270 bottom
CI1  0.1U_0402_10V7K  [C_0402]  21.88 87.34 180 top
CI2  0.1U_0402_10V7K  [C_0402]  21.88 88.23 180 top
CI3  0.1U_0402_10V7K  [C_0402]  21.88 89.24 180 top
CI4  0.1U_0402_10V7K  [C_0402]  21.88 90.13 180 top
CI5  0.1U_0402_10V7K  [C_0402]  21.94 83.46 180 top
CI6  0.1U_0402_10V7K  [C_0402]  21.94 84.35 180 top
CI7  0.1U_0402_10V7K  [C_0402]  21.94 85.37 180 top
CI8  0.1U_0402_10V7K  [C_0402]  21.94 86.26 180 top
CI9  .1U_0402_16V7K  [C_0402]  27.64 79.15 270 top
CL1  0.1U_0402_10V7K  [C_0402]  32.98 121.7 270 bottom
CL2  0.1U_0402_10V7K  [C_0402]  33.93 121.7 270 bottom
CL3  0.1U_0402_10V7K  [C_0402]  29.91 116.93 0 bottom
CL4  0.1U_0402_10V7K  [C_0402]  29.91 117.88 0 bottom
CL5  0.1U_0402_25V6  [C_0402]  33.15 114.76 0 top
CL6  0.1U_0402_25V6  [C_0402]  36.66 116.91 90 top
CL7  4.7U_0603_6.3V6K  [C_0603]  36.91 114.06 180 top
CL8  0.1U_0402_25V6  [C_0402]  36.66 115.13 90 top
CL9  1U_0402_6.3V6K  [C_0402]  29.85 123.53 0 bottom
CL10  10P_0402_50V8J  [C_0402]  39.08 118.2 180 bottom
CL11  10P_0402_50V8J  [C_0402]  39.76 117.3 0 bottom
CL12  0.01U_0402_16V7K  [C_0402]  27.69 110.2 0 top
CL13  100P_1206_2KV8J  [C_1206]  20.26 119.44 180 bottom
CL14  0.1U_0402_25V6  [C_0402]  35.85 118.7 180 top
CS1  0.01U_0402_50V7K  [C_0402]  195.13 22.8 270 bottom
CS2  0.01U_0402_50V7K  [C_0402]  194.18 22.81 270 bottom
CS3  0.01U_0402_50V7K  [C_0402]  193.16 22.8 270 bottom
CS4  0.01U_0402_50V7K  [C_0402]  192.21 22.81 270 bottom
CS5  1000P_0402_50V7K  [C_0402]  190.12 17.5 180 bottom
CS6  0.1U_0402_25V6K  [C_0402]  190.12 18.39 180 bottom
CS7  10U_0805_10V6K  [C_0805]  190.74 20.72 180 bottom
CS9  0.01U_0402_50V7K  [C_0402]  192.48 45.88 270 bottom
CS10  0.01U_0402_50V7K  [C_0402]  191.53 45.88 270 bottom
CS11  0.01U_0402_50V7K  [C_0402]  189.5 45.88 270 bottom
CS12  0.01U_0402_50V7K  [C_0402]  188.61 45.88 270 bottom
CS13  1000P_0402_50V7K  [C_0402]  195.48 49.49 180 top
CS14  0.1U_0402_25V6K  [C_0402]  195.48 50.38 180 top
CS15  10U_0805_10V6K  [C_0805]  196.53 49.93 0 top
CS16  0.22U_0402_16V7K  [C_0402]  186.7 18.43 0 top
CS17  0.22U_0402_16V7K  [C_0402]  186.7 19.39 0 top
CS18  0.22U_0402_16V7K  [C_0402]  193.38 18.51 270 top
CS19  0.22U_0402_16V7K  [C_0402]  194.33 18.51 270 top
CU1  .1U_0402_16V7K  [C_0402]  22.83 62.51 180 top
CU2  .1U_0402_16V7K  [C_0402]  22.83 61.62 180 top
CU3  .1U_0402_16V7K  [C_0402]  22.95 40.85 180 top
CU4  .1U_0402_16V7K  [C_0402]  22.95 39.97 180 top
CU5  1U_0402_10V6K  [C_0402]  4.97 27.47 270 bottom
CU6  1U_0402_10V6K  [C_0402]  17.21 63.21 0 top
CU7  1U_0402_10V6K  [C_0402]  17.22 64.09 0 top
CU8  22U_0805_10V6M  [C_0805]  17.67 65.14 90 top
CU9  22U_0805_10V6M  [C_0805]  19.45 65.14 90 top
CU10  100U_1206_6.3V6M  [C_1206]  21.36 65.23 90 top
CU17  .1U_0402_16V7K  [C_0402]  165.91 20.47 270 bottom
CU18  1U_0402_10V6K  [C_0402]  17.15 41.67 0 top
CU19  1U_0402_10V6K  [C_0402]  17.15 42.56 0 top
CU20  22U_0805_10V6M  [C_0805]  19.39 43.62 90 top
CU21  22U_0805_10V6M  [C_0805]  17.61 43.62 90 top
CU22  100U_1206_6.3V6M  [C_1206]  21.36 43.71 90 top
CW1  .1U_0402_16V7K  [C_0402]  52.25 97.27 90 bottom
CW2  .1U_0402_16V7K  [C_0402]  51.36 97.27 90 bottom
CW3  .1U_0402_16V7K  [C_0402]  60.85 104.88 270 top
CW4  .1U_0402_16V7K  [C_0402]  59.96 104.88 270 top
CW5  10U_0603_6.3V6M  [C_0603]  58.82 105.36 270 top
CW6  10U_0603_6.3V6M  [C_0603]  60.72 108.8 180 top
CW7  .1U_0402_16V7K  [C_0402]  60.8 109.88 180 top
CW8  .1U_0402_16V7K  [C_0402]  43.39 109.76 270 top
CW9  10P_0402_50V8J  [C_0402]  44.34 109.76 270 top
CX1  0.1U_0402_10V6K  [C_0402]  221.11 50.19 0 top
CX2  1U_0402_6.3V6K  [C_0402]  214.45 49.04 0 top
CX3  2200P_0402_25V7K  [C_0402]  215.36 51.07 180 top
CX4  0.01U_0402_16V7K  [C_0402]  207.52 42.51 0 bottom
CX5  0.1U_0402_10V6K  [C_0402]  215.61 37.43 180 bottom
CX6  0.1U_0402_10V6K  [C_0402]  207.52 40.73 0 bottom
CX7  0.1U_0402_10V6K  [C_0402]  207.52 41.62 0 bottom
CX8  0.1U_0402_10V6K  [C_0402]  207.52 38.95 0 bottom
CX9  0.1U_0402_10V6K  [C_0402]  216.54 40.28 0 bottom
CX10  0.1U_0402_10V6K  [C_0402]  207.52 39.84 0 bottom
CX11  0.1U_0402_10V6K  [C_0402]  216.54 39.39 0 bottom
CX12  12P_0402_50V8J  [C_0402]  221.11 51.08 0 top
CX13  12P_0402_50V8J  [C_0402]  215.36 50.06 180 top
CZ1  0.1U_0402_10V7K  [C_0402]  135.2 37.15 0 top
CZ2  0.1U_0402_10V7K  [C_0402]  131.91 40.1 270 top
CZ3  470P_0402_50V7K  [C_0402]  134.19 41.02 90 top
CZ4  1U_0402_6.3V6K  [C_0402]  135.79 32.16 270 top
CZ5  0.1U_0402_10V7K  [C_0402]  138.58 34 270 top
CZ6  0.1U_0402_10V7K  [C_0402]  132.62 32.27 180 top
CZ7  0.1U_0402_10V7K  [C_0402]  138.26 35.05 90 top
CZ8  0.1U_0402_25V6  [C_0402]  131.97 25.62 270 top
CZ9  0.1U_0402_10V7K  [C_0402]  169.45 20.15 180 top
CZ10  470P_0402_50V7K  [C_0402]  166.39 20.15 270 top
CZ11  470P_0402_50V7K  [C_0402]  165.5 20.15 270 top
CZ12  0.1U_0402_10V7K  [C_0402]  164.61 20.14 270 top
CZ21  1U_0402_6.3V6K  [C_0402]  131.73 37.2 90 top
CZ22  0.1U_0402_10V7K  [C_0402]  135.12 41.01 90 top
CZ23  1U_0402_6.3V6K  [C_0402]  168.64 25.8 180 top
CZ24  0.1U_0402_10V7K  [C_0402]  169.91 24.57 90 top
CZ25  1U_0402_6.3V6K  [C_0402]  165.92 25.8 0 top
D1  -  [BAS40C_SOT23-3]  35.36 3.33 90 bottom
D2  -  [RB551V-30_SOD323-2]  36.4 7.52 270 top
D3  -  [BAT54C-7-F_SOT23-3]  222.55 22.38 90 top
D4  -  [BAT54C-7-F_SOT23-3]  222.55 22.38 270 bottom
D5  -  [RB551V-30_SOD323-2]  217.82 30.5 0 top
D6  -  [RB551V-30_SOD323-2]  101.43 9.41 90 top
D8  -  [SDMK0340L-7-F_SOD323-2]  184.19 53.59 135 top
DA1  AZ5125-02S.R7G_SOT23-3  [AZ5125-02SPR7G_SOT23-3]  26.6 7.2 270 top
DA2  AZ5125-02S.R7G_SOT23-3  [AZ5125-02SPR7G_SOT23-3]  26.6 3.25 270 top
DA3  -  [BAT54C-7-F_SOT23-3]  19.78 29.29 0 top
DA4  -  [L03ESDL5V0CC3-2_SOT23-3]  18.84 12.09 270 bottom
DA5  AZ5123-02S.R7G_SOT23-3  [AZ5123-02SPR7G_SOT23-3]  18.84 16.15 270 bottom
DA6  -  [PESD5V0U2BT_SOT23-3]  220.36 29.02 180 bottom
DE1  AZ5125-01H.R7G_SOD523-2  [AZ5125-01HPR7G_SOD523-2]  155.6 18.55 270 top
DX1  S DIO(BR) TVWDF1004AD0 DFN ESD  [IP4292CZ10-TBR_XSON10_2P5X1]  218.83 45.82 180 bottom
DX2  -  [RB751S40T1G_SOD523-2]  106.51 34.18 270 top
DX3  -  [RB751S40T1G_SOD523-2]  105.3 33.61 180 top
DZ1  -  [RB751S40T1G_SOD523-2]  89.04 38.68 0 top
DZ2  -  [RB751S40T1G_SOD523-2]  140.23 34.81 90 top
DZ3  -  [RB751S40T1G_SOD523-2]  92.35 22.17 90 top
DZ4  -  [RB751S40T1G_SOD523-2]  84.7 17.2 90 top
DZ5  -  [RB751S40T1G_SOD523-2]  137.13 37.15 90 top
EC2201  0.1U_0402_25V6  [C_0402]  155.53 103.79 180 bottom
EC2202  1000P_0402_50V7K  [C_0402]  203.27 21.93 0 bottom
EC2203  0.1U_0402_25V6  [C_0402]  182.39 49.1 45 bottom
EC2204  1000P_0402_50V7K  [C_0402]  197.12 28.96 90 bottom
EC2205  0.1U_0402_25V6  [C_0402]  165.96 79.77 180 bottom
EC2206  0.1U_0402_25V6  [C_0402]  160.23 46.93 90 bottom
EC2207  1000P_0402_50V7K  [C_0402]  92.98 114.39 270 bottom
EC2208  1000P_0402_50V7K  [C_0402]  182.14 41.6 90 bottom
EC2209  1000P_0402_50V7K  [C_0402]  81.03 112.1 0 bottom
EC2210  0.1U_0402_25V6  [C_0402]  196.17 28.96 90 bottom
EC2211  0.1U_0402_25V6  [C_0402]  226.68 41.46 180 top
EC2212  1000P_0402_50V7K  [C_0402]  226.21 45.41 90 top
EC2213  1000P_0402_50V7K  [C_0402]  93.94 114.39 270 bottom
EC2214  1000P_0402_50V7K  [C_0402]  159.34 46.94 90 bottom
EC2215  1U_0402_10V6K  [C_0402]  166.4 18.38 180 top
EC2216  1U_0402_10V6K  [C_0402]  195.47 27.58 0 top
EC2217  0.1U_0603_25V7K  [C_0603]  145.94 52.09 270 top
EC2218  0.1U_0603_25V7K  [C_0603]  141.51 49.15 315 top
EC2225  1U_0402_10V6K  [C_0402]  90.89 23.46 270 top
EC2226  1U_0402_10V6K  [C_0402]  163.14 17.29 0 top
EC2229  1U_0402_10V6K  [C_0402]  176.49 23.15 270 top
EC2230  1U_0402_10V6K  [C_0402]  155.42 94.02 0 bottom
EC2301  0.1U_0402_25V6  [C_0402]  13.1 10.13 270 top
EC2302  0.1U_0402_25V6  [C_0402]  15.51 24.52 90 top
EC2901  1000P_0402_50V7K  [C_0402]  155.63 109.4 180 top
EC2902  .1U_0402_16V7K  [C_0402]  155.67 107.47 180 top
EC3001  .1U_0402_16V7K  [C_0402]  113.44 10.82 180 bottom
EC3002  .1U_0402_16V7K  [C_0402]  119.33 10.86 90 bottom
EC3201  33P_0402_50V8J  [C_0402]  55.24 98.18 270 bottom
EC3202  33P_0402_50V8J  [C_0402]  54.34 98.18 270 bottom
ED2901  -  [AZ5725-01F_DFN2]  155.64 108.42 180 top
EU2601  -  [L05ESDL5V0NA-4_SLP2510P8-10-9]  18.17 60.17 270 top
EU2602  -  [AZC199-02SPR7G_SOT23-3]  17.77 57.36 270 top
EU2603  -  [L05ESDL5V0NA-4_SLP2510P8-10-9]  18.17 38.52 270 top
EU2604  -  [AZC199-02SPR7G_SOT23-3]  18.09 35.65 270 top
EU3101  -  [L05ESDL5V0NA-4_SLP2510P8-10-9]  195.2 19.63 0 bottom
EU3501  -  [TVWDF1004AD0_DFN9]  30.57 109.32 90 bottom
F1  SMD1812P150TF/24 1.5A UL/CSA/TUV  [F_SMD1812P110TF-24]  228.49 44.97 90 top
F2  1.1A_24V_SMD1812P110TF-24  [F_SMD1812P110TF-24]  229.01 32.41 180 top
F3  0.5A_13.2V_MF-NSMF050-2  [F_MF-NSMF050-2]  122.7 9.95 90 bottom
FD1  FIDUCAL  [FIDUCIAL_C40M80]  45.68 133.24 0 top
FD2  FIDUCAL  [FIDUCIAL_C40M80]  45.68 133.24 180 bottom
FD3  FIDUCAL  [FIDUCIAL_C40M80]  226.14 21.61 0 top
FD4  FIDUCAL  [FIDUCIAL_C40M80]  226.14 21.61 180 bottom
FI1  1.5A_6V_1206L150PR~D  [F_1206L150PR]  29.3 79.14 270 top
H1  HOLEA  [H_3P0-G]  18.4 4.3 0 top
H2  HOLEA  [H_3P0-G]  8.7 122.3 0 top
H3  HOLEA  [H_3P0-G]  141.9 6.3 0 top
H4  HOLEA  [H_3P0-G]  206.6 47.9 0 top
H5  HOLEA  [H_3P0-G]  141.9 61.2 0 top
H6  HOLEA  [H_5P6N]  18.3 94.3 180 bottom
H7  HOLEA  [H_3P0N]  3 122.3 0 top
H11  HOLEA  [H_3P2]  52.3 133.7 0 top
H12  HOLEA  [H_3P2X2P6]  5 3.6 90 top
H21  HOLEA  [H_3P0-G]  166 99.8 0 top
HCPU1  HOLEA  [H_3P7X4P3]  100 85.45 0 top
HCPU2  HOLEA  [H_3P9]  124.3 85.45 0 top
HCPU3  HOLEA  [H_3P7]  100 22.25 0 top
HCPU4  HOLEA  [H_3P7X4P3]  124.3 22.25 90 top
J3D1  ACES_50463-0104A-001  [ACES_50463-0104A-001_10P]  218.99 49.12 0 bottom
JCMOS1  SHORT PADS~D  [SHORTPADS]  88.35 25.55 180 bottom
JDB1  JXT_FP241AH-010GAAM  [JXT_FP241AH-010GAAM_10P]  118.74 8.02 0 top
JDEG1  JXT_FP241AH-010GAAM  [JXT_FP241AH-010GAAM_10P]  129.74 8.02 0 top
JDIMM1  DEREN_40-42271-26001RHF  [DEREN_40-42271-26001RHF_260P-T]  67.25 87.13 270 bottom
JDIMM2  DEREN_40-42261-26001RHF  [DEREN_40-42261-26001RHF_260P-T]  53.05 87.62 90 bottom
JEDP1  ACES_51540-04001-P01  [ACES_51540-04001-P01_40P]  224.07 50.05 270 bottom
JFAN1  JXT_WB247H-004S10M  [JXT_WB247H-004S10M_4P]  182.77 52.09 47.5 bottom
JHDD1  ACES_51625-01201-001  [ACES_51625-01201-001_12P]  199.15 17.15 180 bottom
JHDMI1  CONCR_099AKAC19NBLCNF  [CONCR_099AKAC19NBLCNF_19P]  10.45 82.5 90 bottom
JHP1  YUQIU_PJ753-F07J1BE-B  [YUQIU_PJ753-F07J1BE-B_7P-T]  11.55 13.52 90 bottom
JIOB1  ACES_51524-0160N-001  [ACES_51524-0160N-001_16P]  185.6 17.6 180 bottom
JKB1  STARC_132C30-100020-A2-R  [STARC_132C30-100020-A2-R_30P]  87.8 9.25 180 bottom
JKBBL1  ACES_51575-00401-001  [ACES_51575-00401-001_4P-T]  116.1 8.73 180 bottom
JLAN1  SANTA_130460-N  [SANTA_130460-N_8P-T]  12.85 113.27 90 bottom
JLED1  ACES_51524-0040N-001  [ACES_51524-0040N-001_4P]  153.7 12.28 180 bottom
JODD1  ACES_50673-0120N-001  [ACES_50673-0120N-001_12P-T]  187.5 47.7 180 bottom
JP1  -  [JUMP_43X79]  133.25 30.67 270 top
JP2  PAD-OPEN1X1M  [JUMP_43X39]  132.48 42.18 270 top
JP3  PAD-OPEN1X1M  [JUMP_43X39]  132.01 33.91 0 top
JP4  PAD-OPEN1X3M  [JUMP_43X118]  169.45 17.27 90 top
JP5  PAD-OPEN1X3M  [JUMP_43X118]  162.16 20.41 180 top
JP9  -  [JUMP_43X79]  162.86 25.1 180 top
JP10  -  [JUMP_43X39]  221.14 48.41 180 top
JP11  2MM  [JUMP_43X39]  30.6 121.39 90 bottom
JP12  -  [JUMP_43X79]  194.9 25.93 270 top
JP13  -  [JUMP_43X79]  196.04 46.82 90 top
JPWR1  JXT_FP226H-006S1BM  [JXT_FP226H-006S1BM_6P]  159.15 107.31 90 top
JRTC1  ACES_50271-0020N-001  [ACES_50271-0020N-001_2P]  29.83 5.9 180 bottom
JSPK1  JXT_WB247H-004S10M  [JXT_WB247H-004S10M_4P]  11.8 5.68 180 bottom
JSSD1  ACES_50406-03071-001  [ACES_50406-03071-001_30P]  198.85 13.93 180 top
JTP1  JXT_FP202DH-008M10M  [JXT_FP202DH-008M10M_8P]  104.9 9.65 180 bottom
JUSB1  ACON_TARA4-9K1311  [ACON_TARA4-9K1311_9P]  14.68 63.2 90 bottom
JUSB2  ACON_TARA4-9K1311  [ACON_TARA4-9K1311_9P]  14.68 41.5 90 bottom
JWLAN1  LCN_DAN05-67406-0100  [LCN_DAN05-67406-0100_67P]  43.05 100.18 0 bottom
L1  BLM15BD601SN1D_2P  [MURAT_BLM15BD601SN1D_2P]  135.59 48.02 180 top
L2  BLM15BD601SN1D_2P  [MURAT_BLM15BD601SN1D_2P]  91.27 45.98 0 top
L3  MCM1012B900F06BP_4P  [INPAQ_MCM1012B900F06BP_4P]  221.37 35.39 180 bottom
L4  MCM1012B900F06BP_4P  [INPAQ_MCM1012B900F06BP_4P-NPM]  220.88 26.81 270 bottom
L5  BLM15PX221SN1D_2P  [MURAT_BLM15PX221SN1D_2P]  29.8 25.65 270 top
LI1  HCM1012GH900BP_4P  [INPAQ_HCM1012GH900BP_4P-NPM]  18.32 88.03 0 top
LI2  HCM1012GH900BP_4P  [INPAQ_HCM1012GH900BP_4P-NPM]  18.32 89.94 0 top
LI3  HCM1012GH900BP_4P  [INPAQ_HCM1012GH900BP_4P-NPM]  18.32 86.06 0 top
LI4  HCM1012GH900BP_4P  [INPAQ_HCM1012GH900BP_4P-NPM]  18.32 84.16 0 top
LU1  MCM1012B900F06BP_4P  [INPAQ_MCM1012B900F06BP_4P]  24.03 57.68 0 top
LU2  HCM1012GH900BP_4P  [INPAQ_HCM1012GH900BP_4P-NPM]  19.65 62.31 0 top
LU3  HCM1012GH900BP_4P  [INPAQ_HCM1012GH900BP_4P-NPM]  19.65 60.54 0 top
LU4  MCM1012B900F06BP_4P  [INPAQ_MCM1012B900F06BP_4P]  24.92 35.9 0 top
LU5  HCM1012GH900BP_4P  [INPAQ_HCM1012GH900BP_4P-NPM]  19.71 40.66 0 top
LU6  HCM1012GH900BP_4P  [INPAQ_HCM1012GH900BP_4P-NPM]  19.71 38.88 0 top
LU7  MCM1012B900F06BP_4P  [INPAQ_MCM1012B900F06BP_4P]  179.4 22.38 90 bottom
LU8  MCM1012B900F06BP_4P  [INPAQ_MCM1012B900F06BP_4P]  183.34 22.13 90 bottom
LW1  MCM1012B900F06BP_4P  [INPAQ_MCM1012B900F06BP_4P-NPM]  43.78 97.99 270 bottom
LX1  MCF12102G900-T_4P  [TAIYO_MCF12102G900-T_4P]  218.35 43.97 270 bottom
LX2  MCF12102G900-T_4P  [TAIYO_MCF12102G900-T_4P]  216.47 44.01 270 bottom
NOREF  -  []  100 85.45 0 top
NOREF#2  -  []  124.3 22.25 0 top
NOREF#3  -  []  5 3.6 0 top
NOREF#4  -  []  18.4 4.3 180 top
NOREF#5  -  []  52.3 133.7 0 top
NOREF#6  -  []  78.89 -52.18 0 top
NOREF#7  -  []  82.25 66.3 0 top
NOREF#8  -  []  75.27 43.34 0 top
NOREF#9  -  []  8.7 122.31 0 top
NOREF#10  -  []  124.3 85.45 0 top
NOREF#11  -  []  301.65 35.58 0 top
NOREF#12  -  []  206.6 47.9 0 top
NOREF#13  -  []  82.25 85.12 0 top
NOREF#14  -  []  100 22.25 0 top
NOREF#15  -  []  141.91 6.29 0 top
NOREF#16  -  []  166 99.8 315 top
NOREF#17  -  []  -1.06 166.97 0 top
NOREF#18  -  []  141.9 61.2 0 top
NOREF#19  -  []  298.15 -43.92 180 bottom
NOREF#20  -  []  81.13 29.23 180 bottom
PBATT1  -  [ACES_50458-01001-P01_10P-T]  225.9 17.6 180 bottom
PC1  1000P_0402_50V7K  [C_0402]  78.39 121.18 180 bottom
PC2  0.1U_0402_25V7K  [C_0402]  78.39 122.13 180 bottom
PC3  1000P_0402_50V7K  [C_0402]  83.14 123.32 90 bottom
PC4  0.1U_0402_25V7K  [C_0402]  82.25 123.32 90 bottom
PC7  0.01U_0402_25V7K  [C_0402]  200.55 19.53 270 bottom
PC8  1000P_0402_50V7K  [C_0402]  203.66 15.21 270 bottom
PC14  .1U_0402_16V7K  [C_0402]  179.58 27.47 180 top
PC16  .1U_0402_16V7K  [C_0402]  177.59 21.56 90 top
PC100  1000P_0402_25V8J  [C_0402]  179.34 44.61 270 top
PC102  0.1U_0402_10V7K  [C_0402]  172.36 46.46 270 bottom
PC103  2200P_0402_50V7K  [C_0402]  178.45 44.61 270 bottom
PC104  10U_0805_25V6K  [C_0805]  176.59 45.99 0 top
PC105  10U_0805_25V6K  [C_0805]  176.59 45.95 0 bottom
PC106  22U_0805_6.3V6M  [C_0805]  161.53 40.21 270 bottom
PC107  22U_0805_6.3V6M  [C_0805]  163.3 39.45 270 bottom
PC108  22U_0805_6.3V6M  [C_0805]  160.45 43.13 90 bottom
PC109  22U_0805_6.3V6M  [C_0805]  159.75 40.21 270 bottom
PC110  22U_0805_6.3V6M  [C_0805]  162.24 43.13 90 bottom
PC111  4.7U_0603_6.3V6M  [C_0603]  175.02 41.81 0 top
PC112  680P_0603_50V7K  [C_0603]  166.58 43.08 270 top
PC113  1000P_0402_25V8J  [C_0402]  175.28 39.6 270 bottom
PC114  0.1U_0402_10V7K  [C_0402]  174.9 36.49 270 bottom
PC115  1000P_0402_25V8J  [C_0402]  182.07 34.26 270 top
PC116  2200P_0402_50V7K  [C_0402]  181.18 34.26 270 bottom
PC117  10U_0805_25V6K  [C_0805]  179.69 35.92 0 bottom
PC118  10U_0805_25V6K  [C_0805]  179.7 35.9 0 top
PC119  4.7U_0603_6.3V6M  [C_0603]  176.68 31.46 0 top
PC120  22U_0805_6.3V6M  [C_0805]  174.94 23.2 0 bottom
PC121  22U_0805_6.3V6M  [C_0805]  174.94 24.92 0 bottom
PC122  22U_0805_6.3V6M  [C_0805]  174.94 26.63 0 bottom
PC123  22U_0805_6.3V6M  [C_0805]  170.67 23.71 180 bottom
PC124  22U_0805_6.3V6M  [C_0805]  170.67 25.42 180 bottom
PC125  680P_0603_50V7K  [C_0603]  173.18 30.95 180 top
PC126  4.7U_0603_6.3V6M  [C_0603]  176.23 29.36 270 bottom
PC127  1000P_0402_25V8J  [C_0402]  179.09 29.37 270 bottom
PC128  4.7U_0402_6.3V6M  [C_0402]  181.74 29.36 0 bottom
PC130  0.1U_0402_25V6  [C_0402]  179.34 44.61 270 bottom
PC131  1000P_0402_25V8J  [C_0402]  178.45 44.61 270 top
PC132  0.1U_0402_25V6  [C_0402]  181.18 34.26 270 top
PC133  1000P_0402_25V8J  [C_0402]  182.07 34.26 270 bottom
PC200  0.1U_0402_10V7K  [C_0402]  83.76 104.67 0 bottom
PC201  2200P_0402_50V7K  [C_0402]  81.03 110.22 0 bottom
PC202  0.1U_0402_10V7K  [C_0402]  90.88 107.14 0 bottom
PC203  0.1U_0402_10V7K  [C_0402]  90.88 108.03 0 bottom
PC204  1U_0603_10V6K  [C_0603]  88.12 101.75 90 bottom
PC205  10U_0805_6.3V6K  [C_0805]  84.32 110.32 0 bottom
PC206  10U_0805_25V6K  [C_0805]  80.7 108.03 0 top
PC207  680P_0402_50V7K  [C_0402]  76.17 104.35 180 top
PC208  0.1U_0402_25V6  [C_0402]  81.04 111.16 0 bottom
PC209  1U_0603_10V6K  [C_0603]  91.89 103.14 270 bottom
PC210  0.033U_0402_16V7K  [C_0402]  87.33 109.92 90 bottom
PC211  10U_0805_6.3V6K  [C_0805]  84.39 112.16 0 bottom
PC212  10U_0805_25V6K  [C_0805]  80.7 108.03 0 bottom
PC213  .1U_0402_16V7K  [C_0402]  88.22 109.92 90 bottom
PC214  220P_0402_25V8J  [C_0402]  90.04 109.93 180 bottom
PC215  22U_0603_6.3V6M  [C_0603]  66.71 107.31 90 bottom
PC216  22U_0603_6.3V6M  [C_0603]  65.45 107.32 90 bottom
PC217  22U_0603_6.3V6M  [C_0603]  64.18 107.31 90 bottom
PC218  22U_0603_6.3V6M  [C_0603]  66.71 107.31 90 top
PC219  22U_0603_6.3V6M  [C_0603]  65.45 107.31 90 top
PC220  22U_0603_6.3V6M  [C_0603]  64.18 107.31 90 top
PC230  1000P_0402_25V8J  [C_0402]  81.03 109.33 0 top
PC231  1000P_0402_25V8J  [C_0402]  81.03 109.33 0 bottom
PC301  2200P_0402_50V7K  [C_0402]  155.21 43.34 270 bottom
PC302  0.1U_0402_25V6  [C_0402]  157.88 43.34 270 bottom
PC303  10U_0805_25V6K  [C_0805]  153.88 44.62 270 bottom
PC304  0.1U_0402_25V6  [C_0402]  154.39 40.4 90 bottom
PC305  1U_0402_6.3V6K  [C_0402]  147.28 39.53 270 bottom
PC306  2.2U_0402_6.3V6M  [C_0402]  146.39 39.53 270 bottom
PC307  0.1U_0402_10V7K  [C_0402]  147.72 46.58 270 bottom
PC308  680P_0603_50V7K  [C_0603]  142.39 46.7 180 bottom
PC309  330P_0402_50V7K  [C_0402]  149.93 38.63 0 bottom
PC310  22U_0603_6.3V6M  [C_0603]  140.48 39.41 270 bottom
PC311  22U_0603_6.3V6M  [C_0603]  139.21 39.41 270 bottom
PC312  22U_0603_6.3V6M  [C_0603]  139.85 45.93 90 bottom
PC313  22U_0603_6.3V6M  [C_0603]  138.58 45.93 90 bottom
PC320  2200P_0402_50V7K  [C_0402]  156.99 43.34 270 bottom
PC321  0.1U_0402_25V6  [C_0402]  156.1 43.34 270 bottom
PC501  22U_0603_6.3V6M  [C_0603]  159.34 37.34 0 bottom
PC502  0.1U_0402_10V7K  [C_0402]  161.7 32.79 180 bottom
PC503  22P_0402_50V8J  [C_0402]  159.92 32.79 180 bottom
PC504  680P_0402_50V7K  [C_0402]  166.01 32.33 90 top
PC505  22U_0603_6.3V6M  [C_0603]  163.72 26.82 180 bottom
PC506  22U_0603_6.3V6M  [C_0603]  163.72 28.03 180 bottom
PC507  22U_0603_6.3V6M  [C_0603]  163.72 25.61 180 bottom
PC601  680P_0402_50V7K  [C_0402]  157.07 61.68 180 top
PC602  0.1U_0402_25V6  [C_0402]  166.25 54.7 0 bottom
PC603  1U_0603_10V6K  [C_0603]  161.57 54.75 270 bottom
PC604  0.22U_0603_25V7K  [C_0603]  161.75 53.62 180 top
PC605  47P_0402_50V8J~D  [C_0402]  168.67 54.65 270 top
PC606  33U_25V_M  [C_25CL33LD]  162.26 69.74 180 bottom
PC608  10U_0805_25V6K  [C_0805]  151.37 69.35 180 bottom
PC611  0.22U_0402_16V7K  [C_0402]  151.48 73.99 0 bottom
PC612  10U_0805_25V6K  [C_0805]  151.37 69.36 180 top
PC613  330P_0402_50V8J  [C_0402]  165.36 58.12 0 bottom
PC614  2200P_0402_50V7K  [C_0402]  169.02 55.77 180 bottom
PC616  33P_0402_50V8J  [C_0402]  169 56.64 90 bottom
PC617  220P_0402_50V7K  [C_0402]  168.98 59.97 0 top
PC618  330P_0402_50V7K  [C_0402]  169.96 59.33 180 bottom
PC619  0.01U_0402_50V7K  [C_0402]  169.96 58.44 180 bottom
PC620  0.082U_0402_16V7K  [C_0402]  168.17 59.35 270 bottom
PC621  680P_0402_50V7K  [C_0402]  168.98 57.28 0 top
PC622  680P_0603_50V7K  [C_0603]  147.35 62.62 270 top
PC624  0.068U_0402_16V7K  [C_0402]  168.04 60.27 90 bottom
PC625  330P_0402_50V7K  [C_0402]  164.35 61.12 90 bottom
PC626  0.015U_0402_25V7K  [C_0402]  168.93 60.27 90 bottom
PC627  2200P_0402_50V7K  [C_0402]  168.94 61.17 180 top
PC628  10P_0402_50V8J  [C_0402]  160.54 58.76 0 bottom
PC629  2200P_0402_50V7K  [C_0402]  160.79 61.62 0 bottom
PC630  2200P_0402_50V7K  [C_0402]  158.83 62.56 90 top
PC631  1200P_0402_50V7K  [C_0402]  161.44 56.97 90 bottom
PC632  2200P_0402_25V7K  [C_0402]  158.78 55.97 180 top
PC633  6800P_0402_25V7K  [C_0402]  158.77 58.65 270 top
PC635  0.022U_0402_16V7K  [C_0402]  168.97 63.02 180 top
PC636  33P_0402_50V8J  [C_0402]  163.46 61.12 90 bottom
PC637  0.033U_0402_16V7K  [C_0402]  156.99 58.65 270 top
PC638  0.022U_0402_16V7K  [C_0402]  169.06 63.89 90 top
PC639  2200P_0402_25V7K  [C_0402]  162.45 64.21 90 top
PC640  2200P_0402_25V7K  [C_0402]  157.05 60.81 270 top
PC641  .1U_0402_16V7K  [C_0402]  170.71 62.05 90 bottom
PC642  0.015U_0402_25V7K  [C_0402]  158.34 62.57 180 bottom
PC643  330P_0402_50V7K  [C_0402]  160.54 59.64 0 bottom
PC644  .1U_0402_16V7K  [C_0402]  156.1 55.95 90 top
PC645  .1U_0402_16V7K  [C_0402]  156.55 63.47 270 bottom
PC646  0.068U_0402_16V7K  [C_0402]  158.34 63.46 180 bottom
PC647  680P_0402_50V7K  [C_0402]  166.39 65.16 90 top
PC649  0.01U_0402_50V7K  [C_0402]  158.84 60.79 180 bottom
PC650  0.082U_0402_16V7K  [C_0402]  157.93 59.9 0 bottom
PC651  330P_0402_50V7K  [C_0402]  161.56 65.12 270 top
PC652  330P_0402_50V7K  [C_0402]  157.05 59.89 90 bottom
PC653  0.082U_0402_16V7K  [C_0402]  161.58 63.33 180 top
PC654  0.01U_0402_50V7K  [C_0402]  160.17 65.12 270 top
PC655  0.22U_0402_16V7K  [C_0402]  163.42 80.1 180 bottom
PC656  10U_0805_25V6K  [C_0805]  159.62 72.9 180 top
PC657  10U_0805_25V6K  [C_0805]  159.57 76.48 180 bottom
PC658  10U_0805_25V6K  [C_0805]  159.57 78.19 180 bottom
PC659  0.1U_0402_25V6K~D  [C_0402]  159.24 76.99 180 top
PC660  2200P_0402_50V7K  [C_0402]  159.24 74.29 180 bottom
PC661  1U_0402_10V6K  [C_0402]  162.74 82.37 0 bottom
PC662  680P_0603_50V7K  [C_0603]  151.72 79.72 0 top
PC663  0.22U_0402_16V7K  [C_0402]  153.08 101.69 180 bottom
PC664  10U_0805_25V6K  [C_0805]  149.08 99.5 180 bottom
PC665  10U_0805_25V6K  [C_0805]  149.08 99.5 180 top
PC666  0.1U_0402_25V6K~D  [C_0402]  152.04 88.44 180 bottom
PC667  2200P_0402_50V7K  [C_0402]  152.04 87.55 180 bottom
PC668  1000P_0402_25V8J  [C_0402]  148.94 98.16 180 top
PC669  1U_0402_10V6K  [C_0402]  152.17 103.95 0 bottom
PC670  680P_0603_50V7K  [C_0603]  143.05 100.54 270 top
PC671  0.22U_0402_16V7K  [C_0402]  156.24 91.81 180 bottom
PC672  10U_0805_25V6K  [C_0805]  152.19 89.77 180 bottom
PC673  10U_0805_25V6K  [C_0805]  152.19 89.77 180 top
PC674  1000P_0402_25V8J  [C_0402]  148.94 97.27 180 bottom
